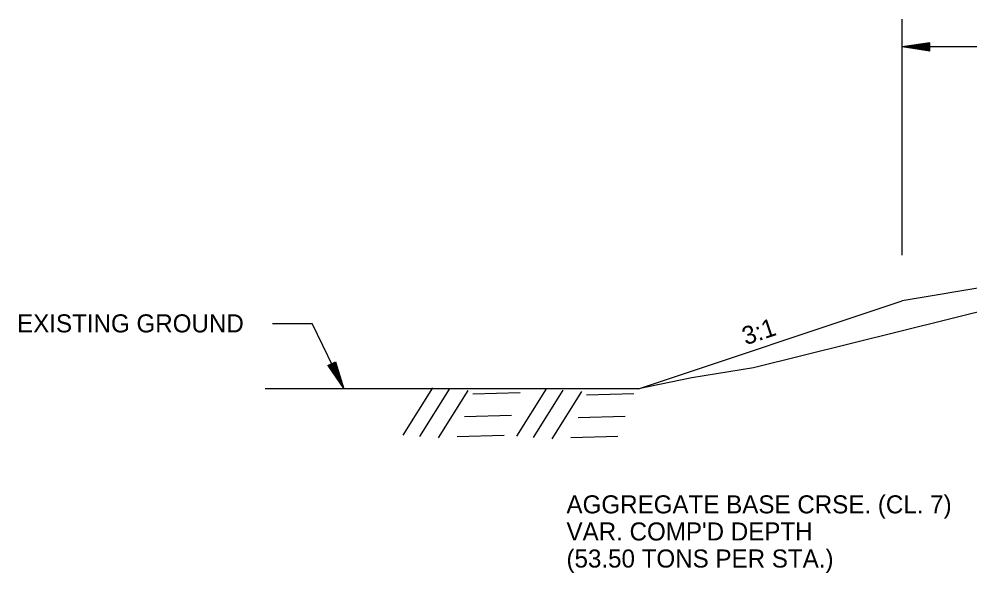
# Model space of a CAD drawing. Extents: x 6848689 to 6848907, y 1900908 to 1901005.
# Drawn here: x 6848689.31 to 6848723.54, y 1900970.46 to 1900990.4 of the extents above; entities that cross this region are included whole.
import ezdxf

# ---------------------------------------------------------------- set-up
doc = ezdxf.new("R2010")
doc.units = 0
for name, color, linetype in [('Default', 7, 'Continuous'), ('R_Draft', 7, 'Continuous'), ('R_No Plot', 7, 'Continuous')]:
    doc.layers.add(name, color=color, linetype=linetype)

msp = doc.modelspace()

# ---------------------------------------------------------------- linework, layer by layer
at = {"layer": 'Default'}
for p, q in [((6848731.103, 1900981.921), (6848721.097, 1900980.254)), ((6848711.61, 1900977.091), (6848721.097, 1900980.254)), ((6848711.61, 1900977.091), (6848698.176, 1900977.091))]:
    msp.add_line(p, q, dxfattribs=at)
msp.add_lwpolyline([(6848726.329, 1900980.467), (6848715.752, 1900977.846), (6848713.532, 1900977.478), (6848711.61, 1900977.091)], dxfattribs=at)
at = {"layer": 'R_Draft'}
for p, q in [((6848722.099, 1900989.546), (6848721.099, 1900989.396)), ((6848722.099, 1900989.246), (6848721.099, 1900989.396)), ((6848722.099, 1900989.521), (6848721.266, 1900989.396)), ((6848722.099, 1900989.271), (6848721.266, 1900989.396)), ((6848722.099, 1900989.496), (6848721.438, 1900989.396)), ((6848722.099, 1900989.297), (6848721.438, 1900989.396)), ((6848722.099, 1900989.471), (6848721.605, 1900989.396)), ((6848722.099, 1900989.322), (6848721.605, 1900989.396)), ((6848722.099, 1900989.445), (6848721.774, 1900989.396)), ((6848722.099, 1900989.348), (6848721.774, 1900989.396)), ((6848722.099, 1900989.42), (6848721.941, 1900989.396)), ((6848722.099, 1900989.373), (6848721.941, 1900989.396)), ((6848722.099, 1900989.246), (6848722.099, 1900989.546)), ((6848698.438, 1900979.436), (6848699.861, 1900979.436)), ((6848700.434, 1900977.924), (6848700.703, 1900978.055)), ((6848700.434, 1900977.924), (6848701.008, 1900977.091)), ((6848700.456, 1900977.935), (6848700.935, 1900977.241)), ((6848700.479, 1900977.946), (6848700.859, 1900977.396)), ((6848700.502, 1900977.957), (6848700.786, 1900977.545)), ((6848700.525, 1900977.968), (6848700.711, 1900977.698)), ((6848700.547, 1900977.979), (6848700.638, 1900977.848)), ((6848700.59, 1900978), (6848700.638, 1900977.848)), ((6848700.613, 1900978.011), (6848700.711, 1900977.698)), ((6848700.635, 1900978.022), (6848700.786, 1900977.545)), ((6848700.658, 1900978.033), (6848700.859, 1900977.396)), ((6848700.681, 1900978.044), (6848700.935, 1900977.241)), ((6848700.703, 1900978.055), (6848701.008, 1900977.091))]:
    msp.add_line(p, q, dxfattribs=at)
at = {"layer": 'R_No Plot'}
for p, q in [((6848721.097, 1900981.9), (6848721.097, 1900990.4)), ((6848735.099, 1900989.396), (6848721.099, 1900989.396)), ((6848701.008, 1900977.091), (6848699.861, 1900979.436)), ((6848703.145, 1900975.418), (6848704.212, 1900977.125)), ((6848703.745, 1900975.369), (6848704.812, 1900977.077)), ((6848707.237, 1900975.38), (6848708.304, 1900977.087)), ((6848704.414, 1900975.323), (6848705.482, 1900977.03)), ((6848705.653, 1900976.911), (6848707.349, 1900976.957)), ((6848707.837, 1900975.331), (6848708.904, 1900977.039)), ((6848708.506, 1900975.285), (6848709.574, 1900976.992)), ((6848709.745, 1900976.873), (6848711.441, 1900976.919)), ((6848705.347, 1900976.093), (6848707.043, 1900976.139)), ((6848709.439, 1900976.055), (6848711.135, 1900976.1)), ((6848705.08, 1900975.374), (6848706.776, 1900975.419)), ((6848709.172, 1900975.336), (6848710.868, 1900975.381))]:
    msp.add_line(p, q, dxfattribs=at)

# ---------------------------------------------------------------- texts
at = {"layer": 'R_Draft'}
for s, p in [('EXISTING GROUND', (6848689.244, 1900979.117)), ('AGGREGATE BASE CRSE. (CL. 7)', (6848709.02, 1900972.601)), ("VAR. COMP'D DEPTH", (6848709.02, 1900971.626)), ('(53.50 TONS PER STA.)', (6848709.02, 1900970.651))]:
    msp.add_text(s, height=0.65, dxfattribs=at).set_placement(p)
msp.add_text('3:1', height=0.65, rotation=18.435, dxfattribs=at).set_placement((6848715.471, 1900978.651))

doc.saveas('drawing.dxf')
